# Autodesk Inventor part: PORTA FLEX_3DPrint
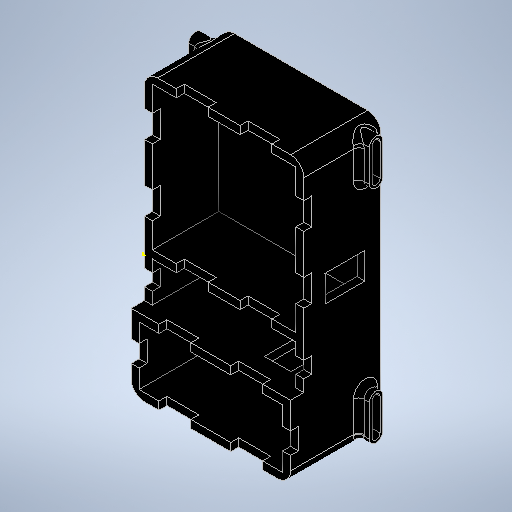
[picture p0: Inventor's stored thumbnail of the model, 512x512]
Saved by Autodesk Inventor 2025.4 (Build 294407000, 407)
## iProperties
Created: 2026-06
Part Number: PORTA FLEX_3DPrint
Material: Generic
Document SubType Name: Modeling
Designer: PC
Density: 1 g/cm^3
Appearance: Default
Author: PC
Part Number: PORTA SEN-FLEX
Appearance: Anodized - Black
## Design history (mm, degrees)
sketch "Sketch1"
  geometry: L1 (0, 0)-(60, 0); L2 (60, 0)-(60, 60); L3 (60, 60)-(0, 60); L4 (0, 60)-(0, 0); L5 (0, 0)-(60, 0); L6 (60, 0)-(60, -15); L7 (60, -15)-(0, -15); L8 (0, -15)-(0, 0); L9 (0, -15)-(60, -15); L10 (60, -15)-(60, -40); L11 (60, -40)-(0, -40); L12 (0, -40)-(0, -15); L13 (0, 60)-(3, 60); L14 (3, 60)-(3, 0); L15 (3, 0)-(0, 0); L16 (0, 0)-(0, 60); L17 (60, 60)-(57, 60); L18 (57, 60)-(57, 0); L19 (57, 0)-(60, 0); L20 (60, 0)-(60, 60); L21 (0, 60)-(60, 60); L22 (60, 60)-(60, 57); L23 (60, 57)-(0, 57); L24 (0, 57)-(0, 60); L25 (0, 0)-(3, 0); L26 (3, 0)-(3, -40); L27 (3, -40)-(0, -40); L28 (0, -40)-(0, 0); L29 (57, 0)-(60, 0); L30 (60, 0)-(60, -40); L31 (60, -40)-(57, -40); L32 (57, -40)-(57, 0); L33 (0, 0)-(60, 0); L34 (60, 0)-(60, 3); L35 (60, 3)-(0, 3); L36 (0, 3)-(0, 0); L37 (0, -15)-(60, -15); L38 (60, -15)-(60, -18); L39 (60, -18)-(0, -18); L40 (0, -18)-(0, -15); L41 (0, -40)-(60, -40); L42 (60, -40)-(60, -43); L43 (60, -43)-(0, -43); L44 (0, -43)-(0, -40); 16 further points
  constraints: 88 end point, 22 parallel, 11 horizontal, 11 perpendicular, 9 point on line
  dimensions: "d0" = 60 distance of L3.end L2.end; "d1" = 60 distance of L2.end L1.end; "d2" = 15 distance of L5.end L6.end; "d3" = 25 distance of L9.end L10.end; "d4" = 3 distance of L14.end L15.end; "d5" = 3 distance of L19.end L18.end; "d6" = 3 distance of L21.end L22.end; "d7" = 3 distance of L26.end L27.end; "d8" = 3 distance of L34.end L33.end; "d9" = 3 distance of L37.end L38.end; "d10" = 3 distance of L41.end L42.end
extrude "Extrusion1" new body sketch "Sketch1" distance "d11" = 25; taper "d12" = 0 deg
extrude "Extrusion2" join sketch "Sketch1" distance "d13" = 30; taper "d14" = 0 deg
extrude "Extrusion3" join sketch "Sketch1" distance "d15" = 4; taper "d16" = 0 deg
sketch "Sketch2"
  geometry: L1 (25, -25)-(-5, -25) reference; L2 (23.172, -25)-(23.172, -25); L3 (24.672, -23.5)-(24.672, -11.5); L4 (23.172, -10)-(23.172, -10); L5 (21.672, -11.5)-(21.672, -23.5); L6 (20.672, -23.5)-(20.672, -11.5); L7 (25.672, -11.5)-(25.672, -23.5); A1 r 1.5 centre (23.172, -23.5) between (21.672, -23.5) and (23.172, -25); A2 r 1.5 centre (23.172, -23.5) between (23.172, -25) and (24.672, -23.5); A3 r 1.5 centre (23.172, -11.5) between (23.172, -10) and (21.672, -11.5); A4 r 1.5 centre (23.172, -11.5) between (24.672, -11.5) and (23.172, -10); A5 r 2.5 centre (23.172, -23.5) between (20.672, -23.5) and (25.672, -23.5); A6 r 2.5 centre (23.172, -11.5) between (20.672, -11.5) and (25.672, -11.5); 7 further points
  constraints: 12 end point, 12 point on circle, 10 tangent, 9 point on line, 6 centre point, 3 equal radius, 2 coincident, 2 parallel, 1 horizontal, 1 perpendicular
  dimensions: "d17" = 3 distance of point (21.672, -10) point (24.672, -10); "d18" = 15 distance of point (24.672, -10) point (24.672, -25); "d19" = 1.5 radius of A1; "d20" = 5 diameter of A5; "d21" = 5 diameter of A6
extrude "Extrusion4" join sketch "Sketch2" distance "d22" = 4; taper "d23" = 0 deg
sketch "Sketch3"
  geometry: 1 further point
workplane "Work Plane1"
mirror "Mirror1"
workplane "Work Plane2"
mirror "Mirror2"
sketch "Sketch4"
  geometry: 1 further point
sketch "Sketch5"
  geometry: L1 (0, -43)-(60, -43) reference; L2 (57, -40)-(3, -40) reference; L3 (10.5, -43)-(22.5, -43); L4 (22.5, -43)-(22.5, -40); L5 (22.5, -40)-(10.5, -40); L6 (10.5, -40)-(10.5, -43); L7 (37.5, -43)-(49.5, -43); L8 (49.5, -43)-(49.5, -40); L9 (49.5, -40)-(37.5, -40); L10 (37.5, -40)-(37.5, -43); L11 (0, -15)-(0, -43) reference; L12 (60, -43)-(60, -15) reference; L13 (0, -29)-(12.499, -29); L14 (10.5, -43)-(22.5, -43); L15 (22.5, -43)-(22.5, -40); L16 (22.5, -40)-(10.5, -40); L17 (10.5, -40)-(10.5, -43); L18 (37.5, -43)-(49.5, -43); L19 (49.5, -43)-(49.5, -40); L20 (49.5, -40)-(37.5, -40); L21 (37.5, -40)-(37.5, -43); L22 (3, -40)-(3, -18) reference; L23 (0, -29)-(3, -29); L24 (3, -29)-(3, -33); L25 (3, -33)-(0, -33); L26 (0, -33)-(0, -29); L27 (57, -18)-(57, -40) reference; L28 (57, -29)-(60, -29); L29 (60, -29)-(60, -33); L30 (60, -33)-(57, -33); L31 (57, -33)-(57, -29); L32 (0, -15)-(60, -15); L33 (57, -18)-(3, -18); L34 (22.5, -15)-(22.5, -18); L35 (37.5, -18)-(37.5, -15); L36 (37.5, -18)-(37.5, -15); L37 (37.5, -15)-(49.5, -15); L38 (49.5, -15)-(49.5, -18); L39 (49.5, -18)-(37.5, -18); L40 (49.5, -18)-(37.5, -18); L41 (49.5, -15)-(49.5, -18); L42 (57, -25)-(57, -29); L43 (60, -29)-(60, -25); L44 (60, -25)-(57, -25); L45 (37.5, -15)-(49.5, -15); L46 (10.5, -15)-(22.5, -15); L47 (22.5, -18)-(10.5, -18); L48 (10.5, -18)-(10.5, -15); L49 (22.5, -15)-(22.5, -18); L50 (10.5, -15)-(22.5, -15); L51 (22.5, -18)-(10.5, -18); L52 (10.5, -18)-(10.5, -15); L53 (3, -29)-(3, -25); L54 (3, -25)-(0, -25); L55 (0, -25)-(0, -29); 25 further points
  constraints: 98 end point, 20 symmetric about line, 12 parallel, 10 point on line, 7 horizontal, 6 midpoint, 6 perpendicular
  dimensions: "d26" = 12 distance of L5.end L4.end; "d27" = 12 distance of L9.end L8.end; "d28" = 15 distance of point (37.5, -41.5) point (22.5, -41.5); "d29" = 10.5 distance from line of L11 point (10.5, -41.5) (= d30); "d30" = 10.5 distance from line of L12 point (49.5, -41.5) (derived); "d31" = 4 distance of L23.end L24.end
extrude "Extrusion5" cut sketch "Sketch5" distance "d32" = 3; taper "d33" = 0 deg
fillet "Fillet1" dims "d34" = 5
feature "Face Fillet1" dims "d35" = 2
feature "Face Fillet2" dims "d36" = 2
feature "Face Fillet3" dims "d37" = 2
feature "Face Fillet4" dims "d38" = 1.99
sketch "Sketch6"
  geometry: L1 (0, 55)-(0, -15) reference; L2 (3, 3)-(3, 57) reference; L3 (0, 12.5)-(3, 12.5); L4 (3, 12.5)-(3, 22.5); L5 (3, 22.5)-(0, 22.5); L6 (0, 22.5)-(0, 12.5); L7 (0, 37.5)-(3, 37.5); L8 (3, 37.5)-(3, 47.5); L9 (3, 47.5)-(0, 47.5); L10 (0, 47.5)-(0, 37.5); L11 (3, 0)-(57, 0) reference; L12 (55, 60)-(5, 60) reference; L13 (57, 3)-(3, 3) reference; L14 (12, 0)-(24, 0); L15 (24, 0)-(24, 3); L16 (24, 3)-(12, 3); L17 (12, 3)-(12, 0); L18 (30, 0)-(30, 22.5); L19 (3, 57)-(57, 57) reference; L20 (12, 60)-(24, 60); L21 (24, 60)-(24, 57); L22 (24, 57)-(12, 57); L23 (12, 57)-(12, 60); L24 (57, 47.5)-(60, 47.5); L25 (57, 37.5)-(57, 47.5); L26 (60, 37.5)-(57, 37.5); L27 (60, 47.5)-(60, 37.5); L28 (57, 3)-(57, 57); L29 (48, 57)-(48, 60); L30 (36, 60)-(36, 57); L31 (48, 60)-(36, 60); L32 (36, 57)-(48, 57); L33 (60, 12.5)-(57, 12.5); L34 (57, 12.5)-(57, 22.5); L35 (57, 22.5)-(60, 22.5); L36 (60, 22.5)-(60, 12.5); L37 (36, 3)-(48, 3); L38 (36, 0)-(36, 3); L39 (48, 0)-(36, 0); L40 (48, 3)-(48, 0); 31 further points
  constraints: 68 end point, 23 symmetric about line, 11 point on line, 8 parallel, 6 midpoint, 4 horizontal, 4 perpendicular, 1 vertical
  dimensions: "d39" = 10 distance of L4.end L3.end; "d40" = 10 distance of L8.end L7.end; "d41" = 15 distance of point (1.5, 37.5) point (1.5, 22.5); "d42" = 12.5 distance from line of L11 point (1.5, 12.5) (= d43); "d43" = 12.5 distance from line of L12 point (1.5, 47.5) (derived); "d44" = 12 distance of L16.end L15.end; "d45" = 12 distance from line of L1 point (12, 1.5)
extrude "Extrusion6" cut sketch "Sketch6" distance "d46" = 3; taper "d47" = 0 deg
sketch "Sketch7"
  geometry: L1 (0, -38)-(0, 55) reference; L2 (3, -15)-(3, 0) reference; L3 (0, -10.5)-(3, -10.5); L4 (3, -10.5)-(3, -4.5); L5 (3, -4.5)-(0, -4.5); L6 (0, -4.5)-(0, -10.5); L7 (3, -18)-(10.5, -18) reference; L8 (12, 3)-(3, 3) reference; L9 (3, -18)-(57, -18) reference; L10 (30, -18)-(30, -5.135); L11 (60, -10.5)-(57, -10.5); L12 (57, -10.5)-(57, -4.5); L13 (57, -4.5)-(60, -4.5); L14 (60, -4.5)-(60, -10.5); 8 further points
  constraints: 18 end point, 6 symmetric about line, 4 midpoint, 2 parallel, 2 point on line, 1 horizontal, 1 perpendicular, 1 vertical
  dimensions: "d48" = 6 distance of L4.end L3.end; "d49" = 7.5 vertical distance of point (1.5, -10.5) point (6.75, -18) (= d50); "d50" = 7.5 distance from line of L8 point (1.5, -4.5) (derived)
extrude "Extrusion7" cut sketch "Sketch7" distance "d51" = 3; taper "d52" = 0 deg
sketch "Sketch8"
  geometry: L1 (37.786, 20.627)-(47.786, 20.627); L2 (47.786, 20.627)-(47.786, 5.627); L3 (47.786, 5.627)-(37.786, 5.627); L4 (37.786, 5.627)-(37.786, 20.627); 1 further point
  constraints: 8 end point, 2 parallel, 1 horizontal, 1 perpendicular
  dimensions: "d53" = 10 distance of L2.end L3.end; "d54" = 15 distance of L1.end L2.end
extrude "Extrusion8" cut sketch "Sketch8" distance "d55" = 3; taper "d56" = 0 deg
sketch "Sketch9"
  geometry: L1 (13, 24.845)-(28, 24.845); L2 (28, 24.845)-(28, 34.845); L3 (28, 34.845)-(13, 34.845); L4 (13, 34.845)-(13, 24.845); L5 (5, 10.5)-(5, 27.5) reference; 2 further points
  constraints: 8 end point, 2 parallel, 1 horizontal, 1 midpoint, 1 perpendicular
  dimensions: "d57" = 15 distance of L3.end L2.end; "d58" = 10 distance of L2.end L1.end; "d59" = 8 distance from line of L5 point (13, 29.845)
extrude "Extrusion9" cut sketch "Sketch9" distance "d60" = 3; taper "d61" = 0 deg
body "Solid1"
other parameters: "d25" = -52
